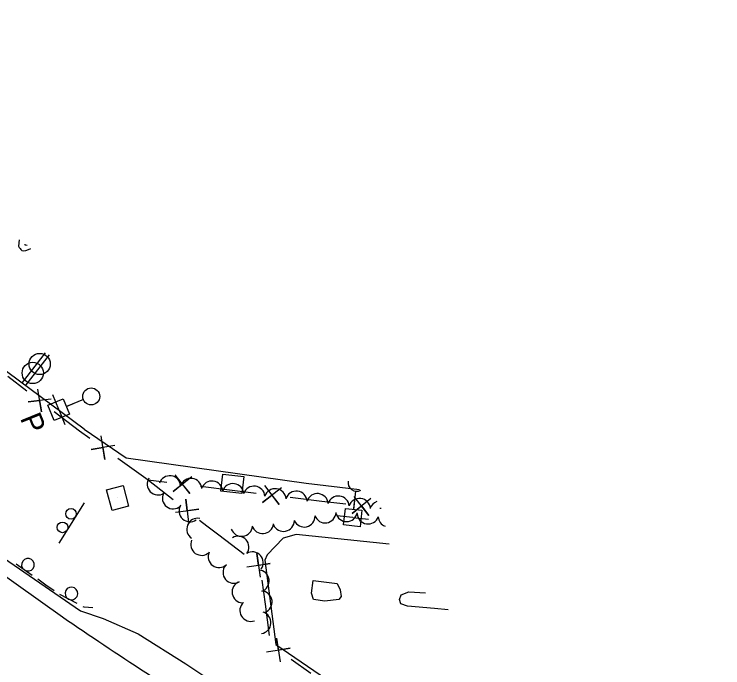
# Model space of a CAD drawing. Extents: x 1746010 to 1754829, y 655801 to 663091.
# Drawn here: x 1748078.7 to 1748412.4, y 661903.4 to 662211.2 of the extents above; entities that cross this region are included whole.
import ezdxf

# ---------------------------------------------------------------- set-up
doc = ezdxf.new("R2010")
doc.units = 0
for name, color, linetype in [('SURVEY - AERIAL SURVEY - Photo Control - Points - Locators', 7, 'Continuous'), ('SURVEY - AERIAL SURVEY - Photo Control - Points - Numbers', 7, 'Continuous'), ('SURVEY - AERIAL SURVEY - Photo Control with Text', 7, 'Continuous'), ('SURVEY - CENTERLINE - Existing Roads - Development', 7, 'Continuous'), ('SURVEY - CENTERLINE - Existing Roads Curve Text', 7, 'Continuous'), ('SURVEY - CENTERLINE - Existing Roads Text', 7, 'Continuous'), ('SURVEY - CENTERLINE - Preliminary - Development', 7, 'Continuous')]:
    doc.layers.add(name, color=color, linetype=linetype)

msp = doc.modelspace()

# ---------------------------------------------------------------- linework, layer by layer
at = {"layer": 'SURVEY - AERIAL SURVEY - Photo Control - Points - Locators'}
for points in [[(1748111.68, 662015.71), (1748050.02, 662061.42), (1747985, 662109.76), (1747949.2, 662136.91), (1747907.89, 662167.74), (1747885.82, 662191.19), (1747883.71, 662193.54), (1747886.26, 662211.22)], [(1748081.11, 662104.97), (1748080.77, 662101.94)], [(1748111.68, 662015.71), (1748131.37, 662002.27), (1748216.13, 661990.33), (1748241.3, 661987.41)], [(1748255.32, 661961.61), (1748211.49, 661966.22), (1748205.36, 661964.35), (1748197.8, 661956.64), (1748196.77, 661954), (1748201.83, 661914.35), (1748276.47, 661863.25), (1748304.31, 661842.91), (1748350.44, 661806.58), (1748401.27, 661769.27), (1748412.36, 661832.91)], [(1748066.45, 661959.99), (1748109.91, 661930.15), (1748120.64, 661926.51), (1748137.02, 661919.36), (1748159.55, 661905.27), (1748212.25, 661870.14), (1748268.84, 661829.36), (1748322.43, 661791.33)], [(1748101.4, 661927.2), (1748067.96, 661950.85)], [(1748225.02, 661934.8), (1748219.7, 661935.46), (1748218.63, 661938.49), (1748219.5, 661944.53)], [(1748219.5, 661944.53), (1748230.71, 661943.05), (1748232.17, 661940.09), (1748232.61, 661936.99), (1748231.56, 661935.47), (1748225.02, 661934.8)], [(1748283.05, 661930.61), (1748276.67, 661931.34), (1748263.85, 661932.33), (1748260.74, 661933.48), (1748260.2, 661935.56), (1748260.89, 661937.71), (1748264.46, 661939.17), (1748272.31, 661938.73)]]:
    msp.add_lwpolyline(points, dxfattribs=at)
for points in [[(1748080.77, 662101.94), (1748082.29, 662099.97), (1748086.59, 662100.92)], [(1748295.79, 661794.96), (1748271.58, 661813.25), (1748243.3, 661833.2), (1748212.42, 661854.75), (1748140.62, 661900.99), (1748101.4, 661927.2)]]:
    msp.add_spline(points, degree=3, dxfattribs=at)
at = {"layer": 'SURVEY - AERIAL SURVEY - Photo Control - Points - Numbers'}
for points in [[(1748087.19, 661946.87), (1748079.65, 661952.14)], [(1748093.66, 661942.34), (1748089.81, 661945.04)], [(1748097.51, 661939.65), (1748093.66, 661942.34)], [(1748108.33, 661933.63), (1748100.17, 661937.89)], [(1748115.79, 661931.63), (1748111.69, 661931.87), (1748111.16, 661932.15)]]:
    msp.add_lwpolyline(points, dxfattribs=at)
for centre, start, end in [((1748085.16, 661951.91), 348.0598, 348.0458), ((1748105.66, 661938.37), 355.4944, 355.4804)]:
    msp.add_arc(centre, 3, start, end, dxfattribs=at)
at = {"layer": 'SURVEY - AERIAL SURVEY - Photo Control with Text'}
for p, q in [((1748082.64, 662037.79), (1748093.52, 662051.69)), ((1748095.2, 662050.76), (1748084.15, 662036.67)), ((1748090.72, 662046.42), (1748090.72, 662046.42)), ((1748087.48, 662042.25), (1748087.48, 662042.25)), ((1748111.6, 661981.03), (1748099.69, 661962.06))]:
    msp.add_line(p, q, dxfattribs=at)
for centre, radius in [((1748090.71, 662046.46), 5), ((1748087.44, 662042.24), 5), ((1748105.46, 661975.86), 2.5), ((1748101.47, 661969.51), 2.5)]:
    msp.add_circle(centre, radius, dxfattribs=at)
at = {"layer": 'SURVEY - CENTERLINE - Existing Roads - Development'}
for points in [[(1748084.75, 662102.28), (1748083.89, 662102.37), (1748083.94, 662102.88)], [(1748084.73, 662033.72), (1748075.66, 662040.63)], [(1748096.14, 662029.87), (1748085.29, 662028.69), (1748090.68, 662029.31), (1748091.57, 662023.9), (1748089.86, 662034.66)], [(1748109.47, 662014.88), (1748097.54, 662023.96)], [(1748114.38, 662011.36), (1748109.47, 662014.88)], [(1748126.03, 662008.05), (1748114.96, 662006.15), (1748120.45, 662007.13), (1748121.38, 662001.55), (1748119.61, 662012.65)], [(1748139.66, 661993.25), (1748127.47, 662001.99)], [(1748150.5, 661990.65), (1748141.82, 661991.7), (1748139.66, 661993.25)], [(1748141.89, 661991.7), (1748153.51, 661982.65)], [(1748162.31, 661993.34), (1748153.51, 661986.35), (1748157.86, 661989.85), (1748161.35, 661985.4), (1748154.47, 661994.29)], [(1748181.37, 661986.89), (1748166.48, 661988.7)], [(1748204.49, 661988.2), (1748195.69, 661981.21), (1748200.04, 661984.71), (1748203.53, 661980.26), (1748196.65, 661989.16)], [(1748192.68, 661985.51), (1748181.37, 661986.89)], [(1748154.61, 661976.61), (1748165.71, 661978.1), (1748160.2, 661977.32), (1748159.58, 661982.86), (1748160.74, 661971.84)], [(1748223.55, 661981.75), (1748208.66, 661983.56)], [(1748234.87, 661980.37), (1748223.55, 661981.75)], [(1748246.68, 661983.06), (1748237.87, 661976.08), (1748242.22, 661979.58), (1748245.71, 661975.12), (1748238.83, 661984.02)], [(1748251.49, 661978.34), (1748250.85, 661978.42)], [(1748166, 661972.94), (1748169.43, 661970.26), (1748174.98, 661966.05)], [(1748174.98, 661966.05), (1748186.91, 661956.96)], [(1748188.17, 661950.86), (1748199.3, 661952.43), (1748193.77, 661951.61), (1748193.01, 661957.21), (1748194.45, 661946.07)], [(1748195.38, 661944.7), (1748196.86, 661933.39)], [(1748196.86, 661933.39), (1748198.8, 661918.52)], [(1748197.53, 661910.86), (1748208.62, 661912.68), (1748203.12, 661911.74), (1748202.23, 661917.32), (1748203.92, 661906.23)], [(1748209.16, 661907.48), (1748218.38, 661900.79)]]:
    msp.add_lwpolyline(points, dxfattribs=at)
at = {"layer": 'SURVEY - CENTERLINE - Existing Roads Curve Text'}
for p, q in [((1748099.67, 662024.96), (1748096.83, 662031.91)), ((1748111.33, 662029.72), (1748103.28, 662026.44)), ((1748099.67, 662024.96), (1748102.5, 662018.02)), ((1748103.65, 662026.59), (1748106.61, 662027.8)), ((1748239.47, 661986.63), (1748238.53, 661977.98)), ((1748238.57, 661978.38), (1748238.92, 661981.56)), ((1748238.11, 661974.1), (1748230.65, 661974.91)), ((1748238.11, 661974.1), (1748245.56, 661973.3))]:
    msp.add_line(p, q, dxfattribs=at)
for points in [[(1748094.58, 662027.1), (1748101.81, 662030.05), (1748104.75, 662022.83), (1748097.53, 662019.88)], [(1748233.81, 661970.65), (1748234.65, 661978.4), (1748242.41, 661977.56), (1748241.57, 661969.81)]]:
    msp.add_lwpolyline(points, close=True, dxfattribs=at)
msp.add_circle((1748114.95, 662031.2), 4, dxfattribs=at)
msp.add_arc((1748239.89, 661990.51), 4, 168.5105, 299.1546, dxfattribs=at)
at = {"layer": 'SURVEY - CENTERLINE - Existing Roads Text'}
for centre, start, end in [((1748146.41, 661989.89), 146.2449, 303.0383), ((1748151.96, 661988.67), 4.3244, 161.1179), ((1748161.89, 661987.45), 4.3244, 161.1179), ((1748171.81, 661986.22), 4.3244, 161.1179), ((1748181.73, 661985), 4.3244, 161.1179), ((1748191.65, 661983.78), 4.3244, 161.1179), ((1748153.58, 661983.37), 154.5254, 311.3188), ((1748201.59, 661982.6), 4.7465, 161.54), ((1748211.52, 661981.45), 4.7465, 161.54), ((1748221.44, 661980.3), 4.7465, 161.54), ((1748231.37, 661979.15), 4.7465, 161.54), ((1748241.3, 661978), 4.7465, 161.54), ((1748251.23, 661976.85), 111.2407, 161.54), ((1748161.45, 661977.25), 148.7532, 305.5467), ((1748215.26, 661974.79), 204.4157, 1.2092), ((1748225.12, 661976.74), 199.8403, 356.6338), ((1748235.22, 661977.34), 192.3694, 349.1628), ((1748245.31, 661976.26), 182.9337, 339.7272), ((1748165.1, 661968.64), 79.2893, 236.0827), ((1748205.5, 661972.76), 202.6401, 359.4336), ((1748255.2, 661974.8), 182.9337, 248.5527), ((1748185.78, 661970.42), 199.3405, 356.1339), ((1748195.71, 661971.7), 196.5026, 353.296), ((1748184.1, 661960.19), 324.053, 120.8464), ((1748166.96, 661961.45), 156.249, 313.0425), ((1748175.13, 661955.69), 156.2421, 313.0355), ((1748190.85, 661952.84), 324.053, 120.8464), ((1748182.15, 661948.31), 141.4324, 298.2258), ((1748193.63, 661944.26), 289.6179, 86.4113), ((1748186.43, 661939.06), 110.7462, 267.5396), ((1748195.02, 661934.36), 289.6179, 86.4113), ((1748190.08, 661930.36), 132.6085, 289.402), ((1748194.47, 661924.63), 277.5367, 74.3301)]:
    msp.add_arc(centre, 5.13, start, end, dxfattribs=at)
at = {"layer": 'SURVEY - CENTERLINE - Preliminary - Development'}
for p, q in [((1748181.41, 661990), (1748181.41, 661990)), ((1748127.42, 661983.34), (1748127.42, 661983.34))]:
    msp.add_line(p, q, dxfattribs=at)
for points in [[(1748176, 661986.58), (1748176.89, 661994.54), (1748186.83, 661993.42), (1748185.93, 661985.47), (1748176, 661986.58)], [(1748122.24, 661987.11), (1748129.96, 661989.22), (1748132.59, 661979.57), (1748124.87, 661977.46), (1748122.24, 661987.11)]]:
    msp.add_lwpolyline(points, dxfattribs=at)

# ---------------------------------------------------------------- texts
at = {"layer": 'SURVEY - CENTERLINE - Existing Roads Curve Text'}
msp.add_text('P', height=10, rotation=292.1921, dxfattribs=at).set_placement((1748081.33, 662020.94))

doc.saveas('drawing.dxf')
